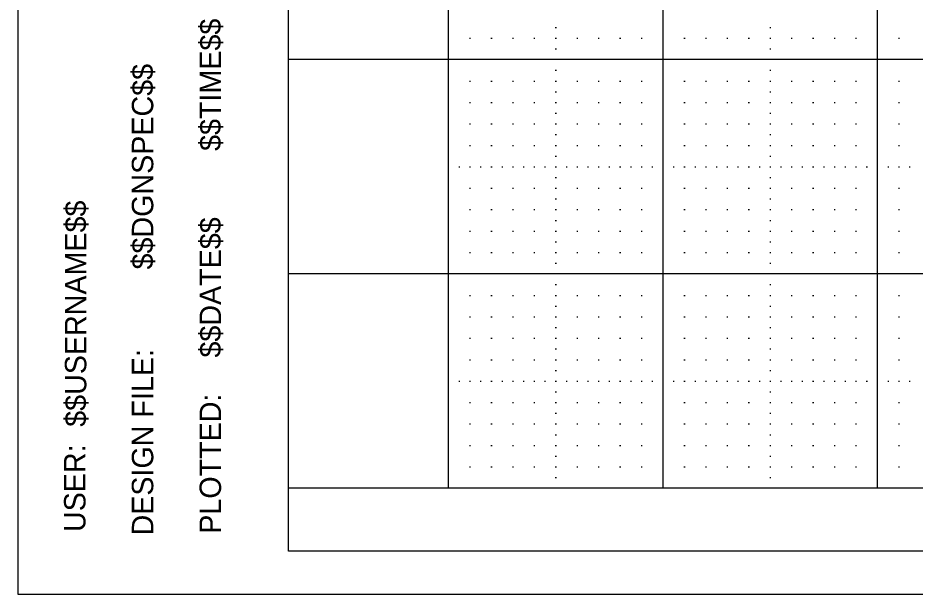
# Model space of a CAD drawing. Extents: x -1.3 to 32.1, y -0.2 to 20.7.
# Drawn here: x -1.263 to 2.92, y -0.2 to 2.487 of the extents above; entities that cross this region are included whole.
import ezdxf

# ---------------------------------------------------------------- set-up
doc = ezdxf.new("R2010")
doc.units = 0
for name, color, linetype in [('Level 1', 7, 'Continuous'), ('Level 4', 7, 'Continuous'), ('Level 5', 7, 'Continuous'), ('Level 63', 7, 'Continuous'), ('R_Border_Dark', 7, 'Continuous')]:
    doc.layers.add(name, color=color, linetype=linetype)

msp = doc.modelspace()

# ---------------------------------------------------------------- linework, layer by layer
at = {"layer": 'Level 1'}
for p, q in [((-0.001, -0.001), (-0.001, 20.545)), ((31.617, -0.001), (-0.001, -0.001))]:
    msp.add_line(p, q, dxfattribs=at)
at = {"layer": 'Level 4'}
msp.add_line((31.617, 0.293), (-0.001, 0.293), dxfattribs=at)
at = {"layer": 'Level 5'}
for p, q in [((1.2425, 2.443), (1.2475, 2.443)), ((2.2425, 2.443), (2.2475, 2.443)), ((0.8425, 2.393), (0.8475, 2.393)), ((0.9425, 2.393), (0.9475, 2.393)), ((1.0425, 2.393), (1.0475, 2.393)), ((1.1425, 2.393), (1.1475, 2.393)), ((1.2425, 2.393), (1.2475, 2.393)), ((1.3425, 2.393), (1.3475, 2.393)), ((1.4425, 2.393), (1.4475, 2.393)), ((1.5425, 2.393), (1.5475, 2.393)), ((1.6425, 2.393), (1.6475, 2.393)), ((1.8425, 2.393), (1.8475, 2.393)), ((1.9425, 2.393), (1.9475, 2.393)), ((2.0425, 2.393), (2.0475, 2.393)), ((2.1425, 2.393), (2.1475, 2.393)), ((2.2425, 2.393), (2.2475, 2.393)), ((2.3425, 2.393), (2.3475, 2.393)), ((2.4425, 2.393), (2.4475, 2.393)), ((2.5425, 2.393), (2.5475, 2.393)), ((2.6425, 2.393), (2.6475, 2.393)), ((2.8425, 2.393), (2.8475, 2.393)), ((1.2425, 2.343), (1.2475, 2.343)), ((2.2425, 2.343), (2.2475, 2.343)), ((1.2425, 2.243), (1.2475, 2.243)), ((2.2425, 2.243), (2.2475, 2.243)), ((0.8425, 2.193), (0.8475, 2.193)), ((0.9425, 2.193), (0.9475, 2.193)), ((1.0425, 2.193), (1.0475, 2.193)), ((1.1425, 2.193), (1.1475, 2.193)), ((1.2425, 2.193), (1.2475, 2.193)), ((1.3425, 2.193), (1.3475, 2.193)), ((1.4425, 2.193), (1.4475, 2.193)), ((1.5425, 2.193), (1.5475, 2.193)), ((1.6425, 2.193), (1.6475, 2.193)), ((1.8425, 2.193), (1.8475, 2.193)), ((1.9425, 2.193), (1.9475, 2.193)), ((2.0425, 2.193), (2.0475, 2.193)), ((2.1425, 2.193), (2.1475, 2.193)), ((2.2425, 2.193), (2.2475, 2.193)), ((2.3425, 2.193), (2.3475, 2.193)), ((2.4425, 2.193), (2.4475, 2.193)), ((2.5425, 2.193), (2.5475, 2.193)), ((2.6425, 2.193), (2.6475, 2.193)), ((2.8425, 2.193), (2.8475, 2.193)), ((1.2425, 2.143), (1.2475, 2.143)), ((2.2425, 2.143), (2.2475, 2.143)), ((0.8425, 2.093), (0.8475, 2.093)), ((0.9425, 2.093), (0.9475, 2.093)), ((1.0425, 2.093), (1.0475, 2.093)), ((1.1425, 2.093), (1.1475, 2.093)), ((1.2425, 2.093), (1.2475, 2.093)), ((1.3425, 2.093), (1.3475, 2.093)), ((1.4425, 2.093), (1.4475, 2.093)), ((1.5425, 2.093), (1.5475, 2.093)), ((1.6425, 2.093), (1.6475, 2.093)), ((1.8425, 2.093), (1.8475, 2.093)), ((1.9425, 2.093), (1.9475, 2.093)), ((2.0425, 2.093), (2.0475, 2.093)), ((2.1425, 2.093), (2.1475, 2.093)), ((2.2425, 2.093), (2.2475, 2.093)), ((2.3425, 2.093), (2.3475, 2.093)), ((2.4425, 2.093), (2.4475, 2.093)), ((2.5425, 2.093), (2.5475, 2.093)), ((2.6425, 2.093), (2.6475, 2.093)), ((2.8425, 2.093), (2.8475, 2.093)), ((1.2425, 2.043), (1.2475, 2.043)), ((2.2425, 2.043), (2.2475, 2.043)), ((0.8425, 1.993), (0.8475, 1.993)), ((0.9425, 1.993), (0.9475, 1.993)), ((1.0425, 1.993), (1.0475, 1.993)), ((1.1425, 1.993), (1.1475, 1.993)), ((1.2425, 1.993), (1.2475, 1.993)), ((1.3425, 1.993), (1.3475, 1.993)), ((1.4425, 1.993), (1.4475, 1.993)), ((1.5425, 1.993), (1.5475, 1.993)), ((1.6425, 1.993), (1.6475, 1.993)), ((1.8425, 1.993), (1.8475, 1.993)), ((1.9425, 1.993), (1.9475, 1.993)), ((2.0425, 1.993), (2.0475, 1.993)), ((2.1425, 1.993), (2.1475, 1.993)), ((2.2425, 1.993), (2.2475, 1.993)), ((2.3425, 1.993), (2.3475, 1.993)), ((2.4425, 1.993), (2.4475, 1.993)), ((2.5425, 1.993), (2.5475, 1.993)), ((2.6425, 1.993), (2.6475, 1.993)), ((2.8425, 1.993), (2.8475, 1.993)), ((1.2425, 1.943), (1.2475, 1.943)), ((2.2425, 1.943), (2.2475, 1.943)), ((0.8425, 1.893), (0.8475, 1.893)), ((0.9425, 1.893), (0.9475, 1.893)), ((1.0425, 1.893), (1.0475, 1.893)), ((1.1425, 1.893), (1.1475, 1.893)), ((1.2425, 1.893), (1.2475, 1.893)), ((1.3425, 1.893), (1.3475, 1.893)), ((1.4425, 1.893), (1.4475, 1.893)), ((1.5425, 1.893), (1.5475, 1.893)), ((1.6425, 1.893), (1.6475, 1.893)), ((1.8425, 1.893), (1.8475, 1.893)), ((1.9425, 1.893), (1.9475, 1.893)), ((2.0425, 1.893), (2.0475, 1.893)), ((2.1425, 1.893), (2.1475, 1.893)), ((2.2425, 1.893), (2.2475, 1.893)), ((2.3425, 1.893), (2.3475, 1.893)), ((2.4425, 1.893), (2.4475, 1.893)), ((2.5425, 1.893), (2.5475, 1.893)), ((2.6425, 1.893), (2.6475, 1.893)), ((2.8425, 1.893), (2.8475, 1.893)), ((1.2425, 1.843), (1.2475, 1.843)), ((2.2425, 1.843), (2.2475, 1.843)), ((0.7925, 1.793), (0.7975, 1.793)), ((0.8425, 1.793), (0.8475, 1.793)), ((0.8925, 1.793), (0.8975, 1.793)), ((0.9425, 1.793), (0.9475, 1.793)), ((0.9925, 1.793), (0.9975, 1.793)), ((1.0425, 1.793), (1.0475, 1.793)), ((1.0925, 1.793), (1.0975, 1.793)), ((1.1425, 1.793), (1.1475, 1.793)), ((1.1925, 1.793), (1.1975, 1.793)), ((1.2425, 1.793), (1.2475, 1.793)), ((1.2925, 1.793), (1.2975, 1.793)), ((1.3425, 1.793), (1.3475, 1.793)), ((1.3925, 1.793), (1.3975, 1.793)), ((1.4425, 1.793), (1.4475, 1.793)), ((1.4925, 1.793), (1.4975, 1.793)), ((1.5425, 1.793), (1.5475, 1.793)), ((1.5925, 1.793), (1.5975, 1.793)), ((1.6425, 1.793), (1.6475, 1.793)), ((1.6925, 1.793), (1.6975, 1.793)), ((1.7925, 1.793), (1.7975, 1.793)), ((1.8425, 1.793), (1.8475, 1.793)), ((1.8925, 1.793), (1.8975, 1.793)), ((1.9425, 1.793), (1.9475, 1.793)), ((1.9925, 1.793), (1.9975, 1.793)), ((2.0425, 1.793), (2.0475, 1.793)), ((2.0925, 1.793), (2.0975, 1.793)), ((2.1425, 1.793), (2.1475, 1.793)), ((2.1925, 1.793), (2.1975, 1.793)), ((2.2425, 1.793), (2.2475, 1.793)), ((2.2925, 1.793), (2.2975, 1.793)), ((2.3425, 1.793), (2.3475, 1.793)), ((2.3925, 1.793), (2.3975, 1.793)), ((2.4425, 1.793), (2.4475, 1.793)), ((2.4925, 1.793), (2.4975, 1.793)), ((2.5425, 1.793), (2.5475, 1.793)), ((2.5925, 1.793), (2.5975, 1.793)), ((2.6425, 1.793), (2.6475, 1.793)), ((2.6925, 1.793), (2.6975, 1.793)), ((2.7925, 1.793), (2.7975, 1.793)), ((2.8425, 1.793), (2.8475, 1.793)), ((2.8925, 1.793), (2.8975, 1.793)), ((1.2425, 1.743), (1.2475, 1.743)), ((2.2425, 1.743), (2.2475, 1.743)), ((0.8425, 1.693), (0.8475, 1.693)), ((0.9425, 1.693), (0.9475, 1.693)), ((1.0425, 1.693), (1.0475, 1.693)), ((1.1425, 1.693), (1.1475, 1.693)), ((1.2425, 1.693), (1.2475, 1.693)), ((1.3425, 1.693), (1.3475, 1.693)), ((1.4425, 1.693), (1.4475, 1.693)), ((1.5425, 1.693), (1.5475, 1.693)), ((1.6425, 1.693), (1.6475, 1.693)), ((1.8425, 1.693), (1.8475, 1.693)), ((1.9425, 1.693), (1.9475, 1.693)), ((2.0425, 1.693), (2.0475, 1.693)), ((2.1425, 1.693), (2.1475, 1.693)), ((2.2425, 1.693), (2.2475, 1.693)), ((2.3425, 1.693), (2.3475, 1.693)), ((2.4425, 1.693), (2.4475, 1.693)), ((2.5425, 1.693), (2.5475, 1.693)), ((2.6425, 1.693), (2.6475, 1.693)), ((2.8425, 1.693), (2.8475, 1.693)), ((1.2425, 1.643), (1.2475, 1.643)), ((2.2425, 1.643), (2.2475, 1.643)), ((0.8425, 1.593), (0.8475, 1.593)), ((0.9425, 1.593), (0.9475, 1.593)), ((1.0425, 1.593), (1.0475, 1.593)), ((1.1425, 1.593), (1.1475, 1.593)), ((1.2425, 1.593), (1.2475, 1.593)), ((1.3425, 1.593), (1.3475, 1.593)), ((1.4425, 1.593), (1.4475, 1.593)), ((1.5425, 1.593), (1.5475, 1.593)), ((1.6425, 1.593), (1.6475, 1.593)), ((1.8425, 1.593), (1.8475, 1.593)), ((1.9425, 1.593), (1.9475, 1.593)), ((2.0425, 1.593), (2.0475, 1.593)), ((2.1425, 1.593), (2.1475, 1.593)), ((2.2425, 1.593), (2.2475, 1.593)), ((2.3425, 1.593), (2.3475, 1.593)), ((2.4425, 1.593), (2.4475, 1.593)), ((2.5425, 1.593), (2.5475, 1.593)), ((2.6425, 1.593), (2.6475, 1.593)), ((2.8425, 1.593), (2.8475, 1.593)), ((1.2425, 1.543), (1.2475, 1.543)), ((2.2425, 1.543), (2.2475, 1.543)), ((0.8425, 1.493), (0.8475, 1.493)), ((0.9425, 1.493), (0.9475, 1.493)), ((1.0425, 1.493), (1.0475, 1.493)), ((1.1425, 1.493), (1.1475, 1.493)), ((1.2425, 1.493), (1.2475, 1.493)), ((1.3425, 1.493), (1.3475, 1.493)), ((1.4425, 1.493), (1.4475, 1.493)), ((1.5425, 1.493), (1.5475, 1.493)), ((1.6425, 1.493), (1.6475, 1.493)), ((1.8425, 1.493), (1.8475, 1.493)), ((1.9425, 1.493), (1.9475, 1.493)), ((2.0425, 1.493), (2.0475, 1.493)), ((2.1425, 1.493), (2.1475, 1.493)), ((2.2425, 1.493), (2.2475, 1.493)), ((2.3425, 1.493), (2.3475, 1.493)), ((2.4425, 1.493), (2.4475, 1.493)), ((2.5425, 1.493), (2.5475, 1.493)), ((2.6425, 1.493), (2.6475, 1.493)), ((2.8425, 1.493), (2.8475, 1.493)), ((1.2425, 1.443), (1.2475, 1.443)), ((2.2425, 1.443), (2.2475, 1.443)), ((0.8425, 1.393), (0.8475, 1.393)), ((0.9425, 1.393), (0.9475, 1.393)), ((1.0425, 1.393), (1.0475, 1.393)), ((1.1425, 1.393), (1.1475, 1.393)), ((1.2425, 1.393), (1.2475, 1.393)), ((1.3425, 1.393), (1.3475, 1.393)), ((1.4425, 1.393), (1.4475, 1.393)), ((1.5425, 1.393), (1.5475, 1.393)), ((1.6425, 1.393), (1.6475, 1.393)), ((1.8425, 1.393), (1.8475, 1.393)), ((1.9425, 1.393), (1.9475, 1.393)), ((2.0425, 1.393), (2.0475, 1.393)), ((2.1425, 1.393), (2.1475, 1.393)), ((2.2425, 1.393), (2.2475, 1.393)), ((2.3425, 1.393), (2.3475, 1.393)), ((2.4425, 1.393), (2.4475, 1.393)), ((2.5425, 1.393), (2.5475, 1.393)), ((2.6425, 1.393), (2.6475, 1.393)), ((2.8425, 1.393), (2.8475, 1.393)), ((1.2425, 1.343), (1.2475, 1.343)), ((2.2425, 1.343), (2.2475, 1.343)), ((1.2425, 1.243), (1.2475, 1.243)), ((2.2425, 1.243), (2.2475, 1.243)), ((0.8425, 1.193), (0.8475, 1.193)), ((0.9425, 1.193), (0.9475, 1.193)), ((1.0425, 1.193), (1.0475, 1.193)), ((1.1425, 1.193), (1.1475, 1.193)), ((1.2425, 1.193), (1.2475, 1.193)), ((1.3425, 1.193), (1.3475, 1.193)), ((1.4425, 1.193), (1.4475, 1.193)), ((1.5425, 1.193), (1.5475, 1.193)), ((1.6425, 1.193), (1.6475, 1.193)), ((1.8425, 1.193), (1.8475, 1.193)), ((1.9425, 1.193), (1.9475, 1.193)), ((2.0425, 1.193), (2.0475, 1.193)), ((2.1425, 1.193), (2.1475, 1.193)), ((2.2425, 1.193), (2.2475, 1.193)), ((2.3425, 1.193), (2.3475, 1.193)), ((2.4425, 1.193), (2.4475, 1.193)), ((2.5425, 1.193), (2.5475, 1.193)), ((2.6425, 1.193), (2.6475, 1.193)), ((2.8425, 1.193), (2.8475, 1.193)), ((1.2425, 1.143), (1.2475, 1.143)), ((2.2425, 1.143), (2.2475, 1.143)), ((0.8425, 1.093), (0.8475, 1.093)), ((0.9425, 1.093), (0.9475, 1.093)), ((1.0425, 1.093), (1.0475, 1.093)), ((1.1425, 1.093), (1.1475, 1.093)), ((1.2425, 1.093), (1.2475, 1.093)), ((1.3425, 1.093), (1.3475, 1.093)), ((1.4425, 1.093), (1.4475, 1.093)), ((1.5425, 1.093), (1.5475, 1.093)), ((1.6425, 1.093), (1.6475, 1.093)), ((1.8425, 1.093), (1.8475, 1.093)), ((1.9425, 1.093), (1.9475, 1.093)), ((2.0425, 1.093), (2.0475, 1.093)), ((2.1425, 1.093), (2.1475, 1.093)), ((2.2425, 1.093), (2.2475, 1.093)), ((2.3425, 1.093), (2.3475, 1.093)), ((2.4425, 1.093), (2.4475, 1.093)), ((2.5425, 1.093), (2.5475, 1.093)), ((2.6425, 1.093), (2.6475, 1.093)), ((2.8425, 1.093), (2.8475, 1.093)), ((1.2425, 1.043), (1.2475, 1.043)), ((2.2425, 1.043), (2.2475, 1.043)), ((0.8425, 0.993), (0.8475, 0.993)), ((0.9425, 0.993), (0.9475, 0.993)), ((1.0425, 0.993), (1.0475, 0.993)), ((1.1425, 0.993), (1.1475, 0.993)), ((1.2425, 0.993), (1.2475, 0.993)), ((1.3425, 0.993), (1.3475, 0.993)), ((1.4425, 0.993), (1.4475, 0.993)), ((1.5425, 0.993), (1.5475, 0.993)), ((1.6425, 0.993), (1.6475, 0.993)), ((1.8425, 0.993), (1.8475, 0.993)), ((1.9425, 0.993), (1.9475, 0.993)), ((2.0425, 0.993), (2.0475, 0.993)), ((2.1425, 0.993), (2.1475, 0.993)), ((2.2425, 0.993), (2.2475, 0.993)), ((2.3425, 0.993), (2.3475, 0.993)), ((2.4425, 0.993), (2.4475, 0.993)), ((2.5425, 0.993), (2.5475, 0.993)), ((2.6425, 0.993), (2.6475, 0.993)), ((2.8425, 0.993), (2.8475, 0.993)), ((1.2425, 0.943), (1.2475, 0.943)), ((2.2425, 0.943), (2.2475, 0.943)), ((0.8425, 0.893), (0.8475, 0.893)), ((0.9425, 0.893), (0.9475, 0.893)), ((1.0425, 0.893), (1.0475, 0.893)), ((1.1425, 0.893), (1.1475, 0.893)), ((1.2425, 0.893), (1.2475, 0.893)), ((1.3425, 0.893), (1.3475, 0.893)), ((1.4425, 0.893), (1.4475, 0.893)), ((1.5425, 0.893), (1.5475, 0.893)), ((1.6425, 0.893), (1.6475, 0.893)), ((1.8425, 0.893), (1.8475, 0.893)), ((1.9425, 0.893), (1.9475, 0.893)), ((2.0425, 0.893), (2.0475, 0.893)), ((2.1425, 0.893), (2.1475, 0.893)), ((2.2425, 0.893), (2.2475, 0.893)), ((2.3425, 0.893), (2.3475, 0.893)), ((2.4425, 0.893), (2.4475, 0.893)), ((2.5425, 0.893), (2.5475, 0.893)), ((2.6425, 0.893), (2.6475, 0.893)), ((2.8425, 0.893), (2.8475, 0.893)), ((1.2425, 0.843), (1.2475, 0.843)), ((2.2425, 0.843), (2.2475, 0.843)), ((0.7925, 0.793), (0.7975, 0.793)), ((0.8425, 0.793), (0.8475, 0.793)), ((0.8925, 0.793), (0.8975, 0.793)), ((0.9425, 0.793), (0.9475, 0.793)), ((0.9925, 0.793), (0.9975, 0.793)), ((1.0425, 0.793), (1.0475, 0.793)), ((1.0925, 0.793), (1.0975, 0.793)), ((1.1425, 0.793), (1.1475, 0.793)), ((1.1925, 0.793), (1.1975, 0.793)), ((1.2425, 0.793), (1.2475, 0.793)), ((1.2925, 0.793), (1.2975, 0.793)), ((1.3425, 0.793), (1.3475, 0.793)), ((1.3925, 0.793), (1.3975, 0.793)), ((1.4425, 0.793), (1.4475, 0.793)), ((1.4925, 0.793), (1.4975, 0.793)), ((1.5425, 0.793), (1.5475, 0.793)), ((1.5925, 0.793), (1.5975, 0.793)), ((1.6425, 0.793), (1.6475, 0.793)), ((1.6925, 0.793), (1.6975, 0.793)), ((1.7925, 0.793), (1.7975, 0.793)), ((1.8425, 0.793), (1.8475, 0.793)), ((1.8925, 0.793), (1.8975, 0.793)), ((1.9425, 0.793), (1.9475, 0.793)), ((1.9925, 0.793), (1.9975, 0.793)), ((2.0425, 0.793), (2.0475, 0.793)), ((2.0925, 0.793), (2.0975, 0.793)), ((2.1425, 0.793), (2.1475, 0.793)), ((2.1925, 0.793), (2.1975, 0.793)), ((2.2425, 0.793), (2.2475, 0.793)), ((2.2925, 0.793), (2.2975, 0.793)), ((2.3425, 0.793), (2.3475, 0.793)), ((2.3925, 0.793), (2.3975, 0.793)), ((2.4425, 0.793), (2.4475, 0.793)), ((2.4925, 0.793), (2.4975, 0.793)), ((2.5425, 0.793), (2.5475, 0.793)), ((2.5925, 0.793), (2.5975, 0.793)), ((2.6425, 0.793), (2.6475, 0.793)), ((2.6925, 0.793), (2.6975, 0.793)), ((2.7925, 0.793), (2.7975, 0.793)), ((2.8425, 0.793), (2.8475, 0.793)), ((2.8925, 0.793), (2.8975, 0.793)), ((1.2425, 0.743), (1.2475, 0.743)), ((2.2425, 0.743), (2.2475, 0.743)), ((0.8425, 0.693), (0.8475, 0.693)), ((0.9425, 0.693), (0.9475, 0.693)), ((1.0425, 0.693), (1.0475, 0.693)), ((1.1425, 0.693), (1.1475, 0.693)), ((1.2425, 0.693), (1.2475, 0.693)), ((1.3425, 0.693), (1.3475, 0.693)), ((1.4425, 0.693), (1.4475, 0.693)), ((1.5425, 0.693), (1.5475, 0.693)), ((1.6425, 0.693), (1.6475, 0.693)), ((1.8425, 0.693), (1.8475, 0.693)), ((1.9425, 0.693), (1.9475, 0.693)), ((2.0425, 0.693), (2.0475, 0.693)), ((2.1425, 0.693), (2.1475, 0.693)), ((2.2425, 0.693), (2.2475, 0.693)), ((2.3425, 0.693), (2.3475, 0.693)), ((2.4425, 0.693), (2.4475, 0.693)), ((2.5425, 0.693), (2.5475, 0.693)), ((2.6425, 0.693), (2.6475, 0.693)), ((2.8425, 0.693), (2.8475, 0.693)), ((1.2425, 0.643), (1.2475, 0.643)), ((2.2425, 0.643), (2.2475, 0.643)), ((0.8425, 0.593), (0.8475, 0.593)), ((0.9425, 0.593), (0.9475, 0.593)), ((1.0425, 0.593), (1.0475, 0.593)), ((1.1425, 0.593), (1.1475, 0.593)), ((1.2425, 0.593), (1.2475, 0.593)), ((1.3425, 0.593), (1.3475, 0.593)), ((1.4425, 0.593), (1.4475, 0.593)), ((1.5425, 0.593), (1.5475, 0.593)), ((1.6425, 0.593), (1.6475, 0.593)), ((1.8425, 0.593), (1.8475, 0.593)), ((1.9425, 0.593), (1.9475, 0.593)), ((2.0425, 0.593), (2.0475, 0.593)), ((2.1425, 0.593), (2.1475, 0.593)), ((2.2425, 0.593), (2.2475, 0.593)), ((2.3425, 0.593), (2.3475, 0.593)), ((2.4425, 0.593), (2.4475, 0.593)), ((2.5425, 0.593), (2.5475, 0.593)), ((2.6425, 0.593), (2.6475, 0.593)), ((2.8425, 0.593), (2.8475, 0.593)), ((1.2425, 0.543), (1.2475, 0.543)), ((2.2425, 0.543), (2.2475, 0.543)), ((0.8425, 0.493), (0.8475, 0.493)), ((0.9425, 0.493), (0.9475, 0.493)), ((1.0425, 0.493), (1.0475, 0.493)), ((1.1425, 0.493), (1.1475, 0.493)), ((1.2425, 0.493), (1.2475, 0.493)), ((1.3425, 0.493), (1.3475, 0.493)), ((1.4425, 0.493), (1.4475, 0.493)), ((1.5425, 0.493), (1.5475, 0.493)), ((1.6425, 0.493), (1.6475, 0.493)), ((1.8425, 0.493), (1.8475, 0.493)), ((1.9425, 0.493), (1.9475, 0.493)), ((2.0425, 0.493), (2.0475, 0.493)), ((2.1425, 0.493), (2.1475, 0.493)), ((2.2425, 0.493), (2.2475, 0.493)), ((2.3425, 0.493), (2.3475, 0.493)), ((2.4425, 0.493), (2.4475, 0.493)), ((2.5425, 0.493), (2.5475, 0.493)), ((2.6425, 0.493), (2.6475, 0.493)), ((2.8425, 0.493), (2.8475, 0.493)), ((1.2425, 0.443), (1.2475, 0.443)), ((2.2425, 0.443), (2.2475, 0.443)), ((0.8425, 0.393), (0.8475, 0.393)), ((0.9425, 0.393), (0.9475, 0.393)), ((1.0425, 0.393), (1.0475, 0.393)), ((1.1425, 0.393), (1.1475, 0.393)), ((1.2425, 0.393), (1.2475, 0.393)), ((1.3425, 0.393), (1.3475, 0.393)), ((1.4425, 0.393), (1.4475, 0.393)), ((1.5425, 0.393), (1.5475, 0.393)), ((1.6425, 0.393), (1.6475, 0.393)), ((1.8425, 0.393), (1.8475, 0.393)), ((1.9425, 0.393), (1.9475, 0.393)), ((2.0425, 0.393), (2.0475, 0.393)), ((2.1425, 0.393), (2.1475, 0.393)), ((2.2425, 0.393), (2.2475, 0.393)), ((2.3425, 0.393), (2.3475, 0.393)), ((2.4425, 0.393), (2.4475, 0.393)), ((2.5425, 0.393), (2.5475, 0.393)), ((2.6425, 0.393), (2.6475, 0.393)), ((2.8425, 0.393), (2.8475, 0.393)), ((1.2425, 0.343), (1.2475, 0.343)), ((2.2425, 0.343), (2.2475, 0.343))]:
    msp.add_line(p, q, dxfattribs=at)
at = {"layer": 'Level 63'}
msp.add_lwpolyline([(-1.263, -0.2005), (32.067, -0.2005), (32.067, 20.7465), (-1.263, 20.7465)], close=True, dxfattribs=at)
msp.add_lwpolyline([(30.745, 8.293), (30.745, 0.293), (0.745, 0.293), (0.745, 8.293)], dxfattribs=at)
at = {"layer": 'R_Border_Dark'}
for p, q in [((0.745, 0.293), (0.745, 8.293)), ((1.745, 0.293), (1.745, 8.293)), ((2.745, 0.293), (2.745, 8.293)), ((31.617, 2.293), (-0.001, 2.293)), ((31.617, 1.293), (-0.001, 1.293))]:
    msp.add_line(p, q, dxfattribs=at)
msp.add_lwpolyline([(30.745, 8.293), (30.745, 0.293), (0.745, 0.293), (0.745, 8.293)], dxfattribs=at)

# ---------------------------------------------------------------- texts
at = {"layer": 'Level 1'}
for s, height, p in [('$$TIME$$', 0.1, (-0.316, 1.867)), ('$$DGNSPEC$$', 0.100002, (-0.632, 1.314)), ('$$USERNAME$$', 0.100002, (-0.944, 0.58)), ('$$DATE$$', 0.1, (-0.316, 0.903)), ('DESIGN FILE:', 0.100002, (-0.632, 0.073)), ('PLOTTED:', 0.1, (-0.316, 0.081)), ('USER:', 0.1, (-0.948, 0.089))]:
    msp.add_text(s, height=height, rotation=90, dxfattribs=at).set_placement(p)

doc.saveas('drawing.dxf')
